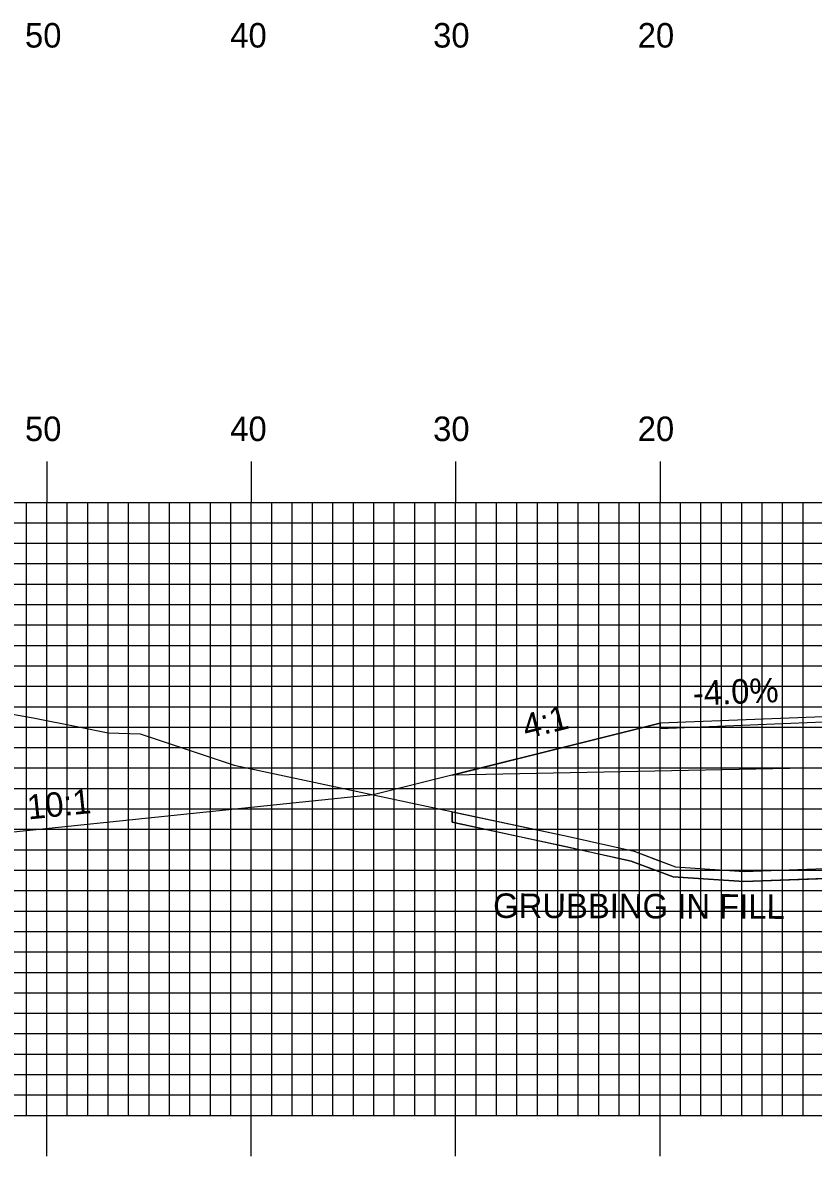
# Model space of a CAD drawing. Extents: x 1754708 to 1755051, y 442591 to 442811.
# Drawn here: x 1754822.3 to 1754861, y 442685.3 to 442740.8 of the extents above; entities that cross this region are included whole.
import ezdxf

# ---------------------------------------------------------------- set-up
doc = ezdxf.new("R2010")
doc.units = 0
for name, color, linetype in [('ANNOTATION', 7, 'Continuous'), ('D_Roadway_Edge_Shoulder', 7, 'Continuous'), ('D_Roadway_SlopeLines', 7, 'Continuous'), ('D_Roadway_SubGrade', 7, 'Continuous'), ('GRUBBING IN FILL', 7, 'Continuous'), ('H_V ANNOTATION', 7, 'Continuous'), ('MAJOR', 7, 'Continuous'), ('MINOR', 7, 'Continuous'), ('S_Roadway_Centerline', 7, 'Continuous')]:
    doc.layers.add(name, color=color, linetype=linetype)

msp = doc.modelspace()

# ---------------------------------------------------------------- linework, layer by layer
at = {"layer": 'D_Roadway_Edge_Shoulder'}
msp.add_lwpolyline([(1754861.517, 442706.822), (1754853.517, 442706.502), (1754853.517, 442706.252), (1754861.517, 442706.572)], close=True, dxfattribs=at)
at = {"layer": 'D_Roadway_SlopeLines'}
msp.add_line((1754839.487, 442702.995), (1754808.436, 442699.789), dxfattribs=at)
msp.add_lwpolyline([(1754853.517, 442706.502), (1754839.487, 442702.995)], dxfattribs=at)
at = {"layer": 'D_Roadway_SubGrade'}
msp.add_lwpolyline([(1754853.517, 442706.252), (1754861.517, 442706.572), (1754861.517, 442706.156), (1754861.517, 442704.322), (1754843.343, 442703.959), (1754853.517, 442706.502)], close=True, dxfattribs=at)
at = {"layer": 'GRUBBING IN FILL'}
msp.add_line((1754843.343, 442702.173), (1754843.343, 442701.662), dxfattribs=at)
msp.add_line((1754843.343, 442702.173), (1754843.343, 442701.662), dxfattribs=at)
msp.add_lwpolyline([(1754843.343, 442701.662), (1754843.343, 442702.173), (1754848.972, 442700.973), (1754852.257, 442700.236), (1754853.265, 442699.855), (1754854.274, 442699.473), (1754855.953, 442699.362), (1754857.632, 442699.25), (1754866.413, 442699.576), (1754873.517, 442699.839), (1754873.517, 442699.338), (1754866.422, 442699.076), (1754857.625, 442698.75), (1754854.166, 442698.979), (1754852.113, 442699.756)], close=True, dxfattribs=at)
msp.add_lwpolyline([(1754843.343, 442701.662), (1754843.343, 442702.173), (1754848.972, 442700.973), (1754852.257, 442700.236), (1754853.265, 442699.855), (1754854.274, 442699.473), (1754855.953, 442699.362), (1754857.632, 442699.25), (1754866.413, 442699.576), (1754873.517, 442699.839), (1754873.517, 442699.338), (1754866.422, 442699.076), (1754857.625, 442698.75), (1754854.166, 442698.979), (1754852.113, 442699.756)], close=True, dxfattribs=at)
msp.add_lwpolyline([(1754843.343, 442701.662), (1754848.865, 442700.485), (1754852.113, 442699.756), (1754854.166, 442698.979), (1754857.625, 442698.75), (1754875.218, 442699.401), (1754875.984, 442699.448), (1754878.886, 442699.328), (1754896.033, 442698.632), (1754900.072, 442698.607), (1754907.451, 442698.155), (1754914.492, 442697.896)], dxfattribs=at)
msp.add_lwpolyline([(1754843.343, 442701.662), (1754848.865, 442700.485), (1754852.113, 442699.756), (1754854.166, 442698.979), (1754857.625, 442698.75), (1754875.218, 442699.401), (1754875.984, 442699.448), (1754878.886, 442699.328), (1754896.033, 442698.632), (1754900.072, 442698.607), (1754907.451, 442698.155), (1754914.492, 442697.896)], dxfattribs=at)
at = {"layer": 'MAJOR'}
for p, q in [((1754823.517, 442719.316), (1754823.517, 442717.312)), ((1754833.517, 442719.316), (1754833.517, 442717.312)), ((1754843.517, 442719.316), (1754843.517, 442717.312)), ((1754853.517, 442719.316), (1754853.517, 442717.312)), ((1754733.517, 442717.312), (1755013.517, 442717.312)), ((1754733.517, 442717.312), (1755013.517, 442717.312)), ((1754823.517, 442687.312), (1754823.517, 442717.312)), ((1754833.517, 442687.312), (1754833.517, 442717.312)), ((1754843.517, 442687.312), (1754843.517, 442717.312)), ((1754853.517, 442687.312), (1754853.517, 442717.312)), ((1754733.517, 442712.312), (1755013.517, 442712.312)), ((1754733.517, 442707.312), (1755013.517, 442707.312)), ((1754733.517, 442702.312), (1755013.517, 442702.312)), ((1754733.517, 442697.312), (1755013.517, 442697.312)), ((1754733.517, 442692.312), (1755013.517, 442692.312)), ((1754733.517, 442687.312), (1755013.517, 442687.312)), ((1754733.517, 442687.312), (1755013.517, 442687.312)), ((1754823.517, 442685.308), (1754823.517, 442687.312)), ((1754833.517, 442685.308), (1754833.517, 442687.312)), ((1754843.517, 442685.308), (1754843.517, 442687.312)), ((1754853.517, 442685.308), (1754853.517, 442687.312))]:
    msp.add_line(p, q, dxfattribs=at)
at = {"layer": 'MINOR'}
for p, q in [((1754822.517, 442687.312), (1754822.517, 442717.312)), ((1754824.517, 442687.312), (1754824.517, 442717.312)), ((1754825.517, 442687.312), (1754825.517, 442717.312)), ((1754826.517, 442687.312), (1754826.517, 442717.312)), ((1754827.517, 442687.312), (1754827.517, 442717.312)), ((1754828.517, 442687.312), (1754828.517, 442717.312)), ((1754829.517, 442687.312), (1754829.517, 442717.312)), ((1754830.517, 442687.312), (1754830.517, 442717.312)), ((1754831.517, 442687.312), (1754831.517, 442717.312)), ((1754832.517, 442687.312), (1754832.517, 442717.312)), ((1754834.517, 442687.312), (1754834.517, 442717.312)), ((1754835.517, 442687.312), (1754835.517, 442717.312)), ((1754836.517, 442687.312), (1754836.517, 442717.312)), ((1754837.517, 442687.312), (1754837.517, 442717.312)), ((1754838.517, 442687.312), (1754838.517, 442717.312)), ((1754839.517, 442687.312), (1754839.517, 442717.312)), ((1754840.517, 442687.312), (1754840.517, 442717.312)), ((1754841.517, 442687.312), (1754841.517, 442717.312)), ((1754842.517, 442687.312), (1754842.517, 442717.312)), ((1754844.517, 442687.312), (1754844.517, 442717.312)), ((1754845.517, 442687.312), (1754845.517, 442717.312)), ((1754846.517, 442687.312), (1754846.517, 442717.312)), ((1754847.517, 442687.312), (1754847.517, 442717.312)), ((1754848.517, 442687.312), (1754848.517, 442717.312)), ((1754849.517, 442687.312), (1754849.517, 442717.312)), ((1754850.517, 442687.312), (1754850.517, 442717.312)), ((1754851.517, 442687.312), (1754851.517, 442717.312)), ((1754852.517, 442687.312), (1754852.517, 442717.312)), ((1754854.517, 442687.312), (1754854.517, 442717.312)), ((1754855.517, 442687.312), (1754855.517, 442717.312)), ((1754856.517, 442687.312), (1754856.517, 442717.312)), ((1754857.517, 442687.312), (1754857.517, 442717.312)), ((1754858.517, 442687.312), (1754858.517, 442717.312)), ((1754859.517, 442687.312), (1754859.517, 442717.312)), ((1754860.517, 442687.312), (1754860.517, 442717.312)), ((1754733.517, 442716.312), (1755013.517, 442716.312)), ((1754733.517, 442715.312), (1755013.517, 442715.312)), ((1754733.517, 442714.312), (1755013.517, 442714.312)), ((1754733.517, 442713.312), (1755013.517, 442713.312)), ((1754733.517, 442711.312), (1755013.517, 442711.312)), ((1754733.517, 442710.312), (1755013.517, 442710.312)), ((1754733.517, 442709.312), (1755013.517, 442709.312)), ((1754733.517, 442708.312), (1755013.517, 442708.312)), ((1754733.517, 442706.312), (1755013.517, 442706.312)), ((1754733.517, 442705.312), (1755013.517, 442705.312)), ((1754733.517, 442704.312), (1755013.517, 442704.312)), ((1754733.517, 442703.312), (1755013.517, 442703.312)), ((1754733.517, 442701.312), (1755013.517, 442701.312)), ((1754733.517, 442700.312), (1755013.517, 442700.312)), ((1754733.517, 442699.312), (1755013.517, 442699.312)), ((1754733.517, 442698.312), (1755013.517, 442698.312)), ((1754733.517, 442696.312), (1755013.517, 442696.312)), ((1754733.517, 442695.312), (1755013.517, 442695.312)), ((1754733.517, 442694.312), (1755013.517, 442694.312)), ((1754733.517, 442693.312), (1755013.517, 442693.312)), ((1754733.517, 442691.312), (1755013.517, 442691.312)), ((1754733.517, 442690.312), (1755013.517, 442690.312)), ((1754733.517, 442689.312), (1755013.517, 442689.312)), ((1754733.517, 442688.312), (1755013.517, 442688.312))]:
    msp.add_line(p, q, dxfattribs=at)
at = {"layer": 'S_Roadway_Centerline'}
msp.add_lwpolyline([(1754820.805, 442707.13), (1754822.854, 442706.77), (1754825.067, 442706.33), (1754826.524, 442706.037), (1754828.077, 442705.984), (1754832.676, 442704.446), (1754848.972, 442700.973), (1754852.257, 442700.236), (1754854.274, 442699.473), (1754857.632, 442699.25), (1754875.194, 442699.901), (1754875.979, 442699.949), (1754878.907, 442699.828), (1754896.045, 442699.132), (1754900.089, 442699.107), (1754907.475, 442698.655), (1754914.615, 442698.392), (1754927.562, 442698.332), (1754934.194, 442698.29), (1754935.534, 442698.264), (1754937.831, 442698.209), (1754947.484, 442697.842), (1754953.043, 442697.646), (1754970.333, 442697)], dxfattribs=at)

# ---------------------------------------------------------------- texts
at = {"layer": 'ANNOTATION'}
for s, rotation, p in [('-4.0%', 2.2906, (1754855.149, 442707.369)), ('4:1', 14.0362, (1754846.966, 442705.726)), ('10:1', 5.895, (1754822.615, 442701.789))]:
    msp.add_text(s, height=1.2, rotation=rotation, dxfattribs=at).set_placement(p)
at = {"layer": 'GRUBBING IN FILL'}
msp.add_text('GRUBBING IN FILL', height=1.2, rotation=359.8142, dxfattribs=at).set_placement((1754845.35, 442696.975))
at = {"layer": 'H_V ANNOTATION'}
for s, p in [('50', (1754822.447, 442739.57)), ('40', (1754832.49, 442739.57)), ('30', (1754842.415, 442739.57)), ('20', (1754852.425, 442739.57)), ('50', (1754822.447, 442720.312)), ('40', (1754832.49, 442720.312)), ('30', (1754842.415, 442720.312)), ('20', (1754852.425, 442720.312))]:
    msp.add_text(s, height=1.2, dxfattribs=at).set_placement(p)

doc.saveas('drawing.dxf')
